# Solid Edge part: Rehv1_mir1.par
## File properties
Author: KULL
Template: Iso Metric Part.par
Last saved by: KULL
Revision: 2
Application: Solid Edge
Accuracy: 0,990
Username: KULL
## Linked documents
Rehv1.par
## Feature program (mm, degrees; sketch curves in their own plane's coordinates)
part copy "CopiedPart_1"
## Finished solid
Body 1: solid body, 650 faces, 1688 edges, 1040 vertices.
  Faces by surface: spline 520, torus 62, cylinder 54, cone 8, plane 6
  Edges by curve: intersection 1040, line 390, curve on surface 130, circle 128
Bounding box of the edges (mm; curved faces can reach further): 42.451 x 100.967 x 100.966, from (-41.2257, -50.4835, -50.483) to (1.2257, 50.4835, 50.483).
Cylindrical faces by radius (mm): R49.482 x1, R50.082 x52, R50.482 x1
Conical faces (half-angle, radius in mm at the cone's reference point): 14.1898 deg R43.1591 x1, 14.1898 deg R43.6493 x1, 14.1898 deg R44.4434 x1, 14.1898 deg R44.864 x1, 75.8102 deg R41.5194 x1, 75.8102 deg R41.7645 x1, 75.8102 deg R43.6493 x1, 75.8102 deg R44.864 x1
Toroidal faces (ring radius, tube radius in mm): R41.9116 r0.6 x2, R41.9116 r1.6 x2, R43.4159 r0.2 x2, R47.1178 r2.3642 x2, R47.1178 r2.9642 x52, R47.1178 r3.3642 x2
Planar faces by outward normal: +x 3, -x 3
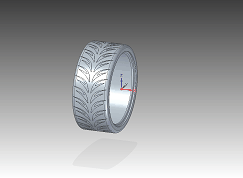
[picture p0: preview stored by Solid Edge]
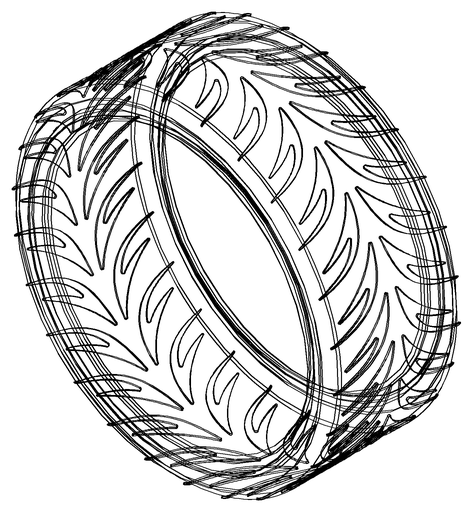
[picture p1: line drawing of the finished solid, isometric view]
